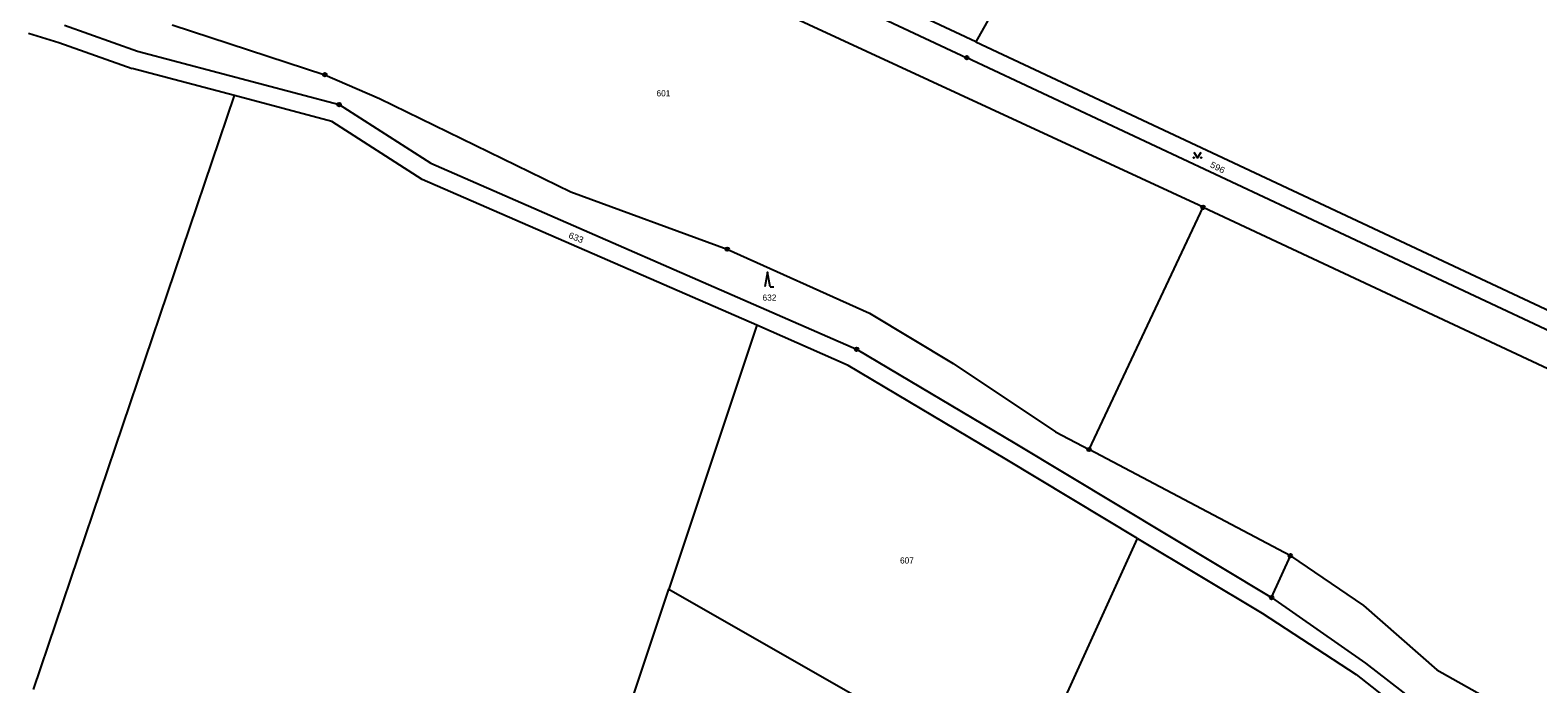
# Model space of a CAD drawing. Extents: x -759947 to -757003, y -1019641 to -1017100.
# Drawn here: x -758964.9 to -758551.5, y -1018953.1 to -1018773.9 of the extents above; entities that cross this region are included whole.
import ezdxf

# ---------------------------------------------------------------- set-up
doc = ezdxf.new("R2010")
doc.units = 0
doc.header["$LTSCALE"] = 0.68
for name, color, linetype, lineweight in [('1', 7, 'Continuous', 25), ('3', 7, 'Continuous', 25), ('8', 7, 'Continuous', 25)]:
    doc.layers.add(name, color=color, linetype=linetype, lineweight=lineweight)
doc.layers.add('2', color=7, linetype='Continuous')

msp = doc.modelspace()

# ---------------------------------------------------------------- linework, layer by layer
at = {"layer": '1'}
for p, q in [((-758627.3, -1018638.55), (-758705.63, -1018777.1)), ((-758705.63, -1018777.1), (-758792.45, -1018736.36)), ((-758794.98, -1018740.7), (-758708.09, -1018781.46)), ((-758643.3, -1018822.47), (-758800.25, -1018749.79)), ((-758955.47, -1018772.55), (-758935.46, -1018779.65)), ((-758925.98, -1018772.45), (-758884.11, -1018786.12)), ((-758965.33, -1018774.78), (-758957.04, -1018777.3)), ((-758957.04, -1018777.3), (-758936.94, -1018784.43)), ((-758705.63, -1018777.1), (-758602.5, -1018825.49)), ((-758935.46, -1018779.65), (-758880.19, -1018794.31)), ((-758604.46, -1018830.09), (-758708.09, -1018781.46)), ((-758908.93, -1018791.86), (-758936.94, -1018784.43)), ((-758884.11, -1018786.12), (-758869.17, -1018792.64)), ((-758963.97, -1018954.72), (-758908.93, -1018791.86)), ((-758882.23, -1018798.94), (-758908.93, -1018791.86)), ((-758880.19, -1018794.31), (-758855.03, -1018810.39)), ((-758869.17, -1018792.64), (-758816.68, -1018818.26)), ((-758857.39, -1018814.82), (-758882.23, -1018798.94)), ((-758855.03, -1018810.39), (-758738.28, -1018861.39)), ((-758765.62, -1018854.84), (-758857.39, -1018814.82)), ((-758816.68, -1018818.26), (-758773.78, -1018833.96)), ((-758674.56, -1018888.89), (-758643.3, -1018822.47)), ((-758643.3, -1018822.47), (-758545.87, -1018868.02)), ((-758602.5, -1018825.49), (-758499.23, -1018873.94)), ((-758501.2, -1018878.54), (-758604.46, -1018830.09)), ((-758773.78, -1018833.96), (-758734.73, -1018851.52)), ((-758734.73, -1018851.52), (-758711.84, -1018865.33)), ((-758765.62, -1018854.84), (-758789.78, -1018927.17)), ((-758740.57, -1018865.84), (-758765.62, -1018854.84)), ((-758738.28, -1018861.39), (-758694.95, -1018887.18)), ((-758697.52, -1018891.47), (-758740.57, -1018865.84)), ((-758711.84, -1018865.33), (-758683.8, -1018884.05)), ((-758683.8, -1018884.05), (-758674.56, -1018888.89)), ((-758694.95, -1018887.18), (-758624.52, -1018929.48)), ((-758619.36, -1018918.02), (-758674.56, -1018888.89)), ((-758661.26, -1018913.25), (-758697.52, -1018891.47)), ((-758692.75, -1018982.61), (-758661.26, -1018913.25)), ((-758661.26, -1018913.25), (-758627.08, -1018933.77)), ((-758624.52, -1018929.48), (-758619.36, -1018918.02)), ((-758619.36, -1018918.02), (-758599.28, -1018931.66)), ((-758805.63, -1018974.63), (-758789.78, -1018927.17)), ((-758789.78, -1018927.17), (-758692.75, -1018982.61)), ((-758624.52, -1018929.48), (-758598.79, -1018947.47)), ((-758627.08, -1018933.77), (-758601.27, -1018950.61)), ((-758599.28, -1018931.66), (-758579.2, -1018949.27)), ((-758598.79, -1018947.47), (-758570.55, -1018969.19)), ((-758601.27, -1018950.61), (-758587.92, -1018961.07)), ((-758579.2, -1018949.27), (-758554.61, -1018963.04))]:
    msp.add_line(p, q, dxfattribs=at)
at = {"layer": '3'}
msp.add_line((-758761.99, -1018844.27), (-758760.994, -1018844.27), dxfattribs=at)
for points in [[(-758645.83, -1018807.379), (-758644.83, -1018808.88), (-758643.83, -1018807.379)], [(-758761.99, -1018844.27), (-758762.74, -1018840.27), (-758763.49, -1018844.27)]]:
    msp.add_lwpolyline(points, dxfattribs=at)
for centre in [(-758645.83, -1018808.8795), (-758643.83, -1018808.8795)]:
    msp.add_circle(centre, 0.1, dxfattribs=at)
at = {"layer": '8'}
for centre, radius in [((-758708.09, -1018781.4599), 0.5), ((-758708.09, -1018781.4599), 0.0303), ((-758884.11, -1018786.1199), 0.5), ((-758884.11, -1018786.1199), 0.0303), ((-758880.19, -1018794.3099), 0.5), ((-758880.19, -1018794.3099), 0.0303), ((-758643.3, -1018822.4699), 0.5), ((-758643.3, -1018822.4699), 0.0303), ((-758773.78, -1018833.9599), 0.5), ((-758773.78, -1018833.9599), 0.0303), ((-758738.28, -1018861.3899), 0.5), ((-758738.28, -1018861.3899), 0.0303), ((-758674.56, -1018888.8899), 0.5), ((-758674.56, -1018888.8899), 0.0303), ((-758619.36, -1018918.0199), 0.5), ((-758619.36, -1018918.0199), 0.0303), ((-758624.52, -1018929.4799), 0.5), ((-758624.52, -1018929.4799), 0.0303)]:
    msp.add_circle(centre, radius, dxfattribs=at)

# ---------------------------------------------------------------- texts
at = {"layer": '2'}
for s, p in [('601', (-758793.16, -1018792.075)), ('632', (-758764.09, -1018848.105)), ('607', (-758726.39, -1018920.155))]:
    msp.add_text(s, height=1.7, dxfattribs=at).set_placement(p)
at = {"layer": '2', "width": 1.1}
for s, rotation, p in [('596', 333, (-758641.542, -1018811.368)), ('633', 338, (-758817.469, -1018830.794))]:
    msp.add_text(s, height=1.7, rotation=rotation, dxfattribs=at).set_placement(p)

doc.saveas('drawing.dxf')
